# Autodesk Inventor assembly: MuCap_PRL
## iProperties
Shininess: 64.0
Length Units: 11269
Angle Units: 11279
Time Units: 11290
Mass Units: 11283
Length Display Precision: 3
Angle Display Precision: 2
Compacted: True
Created: 2004-08
Part Number: MuCap_PRL
Document SubType Name: Assembly
Designer: John Blackburn
Manufacturer: Standard
Standards Organization: Custom
Density: 0.0
Volumn: 0.0
Area: 0.0
PropertySet Name: Model Information
Control State: 0
Master: False
Checked Out: False
Author: John Blackburn
